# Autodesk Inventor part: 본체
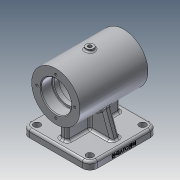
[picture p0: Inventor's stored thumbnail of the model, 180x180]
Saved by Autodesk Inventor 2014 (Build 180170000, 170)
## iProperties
Created: 2019-06
Part Number: 본체
Material: 알루미늄 6061
Document SubType Name: Modeling
Designer: net
Density: 2.71 g/cm^3
Appearance: 알루미늄 - 평지
Mass: 611.033 g
Surface Area: 626.842 cm^2
Volume: 225.474 cm^3
Author: net
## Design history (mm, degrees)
sketch "스케치1"
  geometry: L1 (-45, 0)-(45, 0); L2 (-45, 0)-(-45, 20); L3 (-45, 20)-(-45, 32); L4 (-45, 32)-(45, 32); L5 (45, 32)-(45, 20); L6 (45, 20)-(45, 0); L7 (45, 20)-(30, 20); L8 (30, 20)-(30, 17); L9 (30, 17)-(24, 17); L10 (24, 17)-(24, 25); L11 (24, 25)-(-24, 25); L12 (-24, 25)-(-24, 17); L13 (-24, 17)-(-30, 17); L14 (-30, 17)-(-30, 20); L15 (-30, 20)-(-45, 20); 1 further point
  constraints: 31 end point, 8 parallel, 5 perpendicular, 1 collinear, 1 horizontal, 1 midpoint
  dimensions: "d0" = 90 distance of L1.start L1.end; "d1" = 45 distance of L1.end point (0, 0); "d2" = 34 diameter of L13 L1; "d3" = 50 diameter of L11 L1; "d4" = 40 diameter of L7 L1; "d5" = 34 diameter of L9 L1; "d6" = 40 diameter of L15 L1; "d7" = 64 diameter of L4 L1; "d8" = 15 distance between parallel lines of L2 L14; "d9" = 48 distance between parallel lines of L10 L12; "d11" = 15 distance between parallel lines of L6 L8; "d12" = 24 horizontal distance of point (0, 0) L10.end
revolve "회전1" sketch "스케치1" stored, may be unused: angle "d13" = 90 deg
sketch "스케치2"
  geometry: L1 (0, 0)-(0, -65); L2 (0, -65)-(45, -65); L3 (45, -65)-(45, -55); L4 (45, -55)-(-45, -55); L5 (0, -65)-(-45, -65); L6 (-45, -65)-(-45, -55)
  constraints: 12 end point, 3 perpendicular, 2 parallel, 1 vertical
  dimensions: "d14" = 65 distance of L1.start L1.end; "d15" = 10 distance of L2.end L3.end; "d16" = 90 distance of L3.end L4.end; "d17" = 45 distance of L5.end L1.end
extrude "돌출1" join sketch "스케치2" stored distance "d18" = 90; taper "d19" = 0 deg
sketch "스케치3"
  geometry: L1 (0, 0)-(0, -27.268); L2 (-45, -55)-(45, -55) reference; L3 (0, -27.268)-(0, -55); L4 (0, -27.268)-(-35, -27.268); L5 (-35, -27.268)-(-35, -55); L6 (0, -55)-(-35, -55); L7 (0, -27.268)-(35, -27.268); L8 (35, -27.268)-(35, -55); L9 (0, -55)-(35, -55)
  constraints: 16 end point, 3 perpendicular, 2 collinear, 2 point on line, 1 midpoint, 1 parallel, 1 vertical
  dimensions: "d20" = 35 distance of L1.end L4.end; "d21" = 35 distance of L1.end L7.end; "d22" = 27.26751 distance of L1.start L1.end
extrude "돌출2" join sketch "스케치3" stored distance "d23" = 10; taper "d24" = 0 deg
sketch "스케치4"
  geometry: 1 further point
sketch "스케치5"
  geometry: L1 (45, -55)-(-45, -55) reference; L2 (35, -55)-(23.058, -22.189); L3 (-23.058, -22.189)-(-35, -55); A1 r 32 centre (0, 0) between (23.058, -22.189) and (-23.058, -22.189) reference; 1 further point
  constraints: 4 end point, 2 point on circle, 2 point on line
  dimensions: "d25" = 10 distance of L1.start L2.start; "d26" = 10 distance of L1.end L3.end; "d27" = 110 deg angle of L1 L3; "d28" = 110 deg angle of L1 L2
feature "리브1" dims "d29" = 1, "d30" = 10, "d31" = 0, "d32" = 0, "d33" = 1, "d34" = 1
feature "리브2" dims "d35" = 1, "d36" = 10, "d37" = 0, "d38" = 0, "d39" = 1, "d40" = 1
fillet "모깎기1" dims "d41" = 3
sketch "스케치6"
  geometry: C1 r 20 at (0, 0) reference; C2 r 32 at (0, 0) reference; A1 r 25 centre (0, 0) between (0, 25) and (25, 0); 2 further points
  constraints: 4 point on circle, 2 horizontal alignment, 2 vertical alignment, 1 centre point, 1 coincident
  dimensions: "d42" = 50 diameter of A1
hole "구멍1" sketch "스케치6" at (0, 25), (25, 0), (0, -25), (-25, 0) diameter "d43" = 3.242; stored, may be unused: countersink angle "d47" = 90 deg, drill point angle "d49" = 118 deg; dims "d44" = 7, "d45" = 4, "d46" = 2, "d48" = 9
sketch "스케치7"
  geometry: C1 r 1.621 at (0, -25) reference; C2 r 1.621 at (-25, 0) reference; C3 r 1.621 at (0, 25) reference; C4 r 1.621 at (25, 0) reference; 4 further points
  constraints: 4 coincident
hole "구멍2" sketch "스케치7" at (0, -25), (-25, 0), (0, 25), (25, 0) diameter "d50" = 3.242; stored, may be unused: countersink angle "d54" = 90 deg, drill point angle "d56" = 118 deg; dims "d51" = 7, "d52" = 4, "d53" = 2, "d55" = 9
sketch "스케치8"
  geometry: L1 (0, 0)-(0, 35); L2 (-45, 32)-(45, 32) reference
  constraints: 2 end point, 1 vertical
  dimensions: "d57" = 3 distance from line of L2 L1.end
node "작업 평면1"
sketch "스케치9"
  geometry: C1 r 5 at (0, 0); 1 further point
  constraints: 1 centre point, 1 coincident
  dimensions: "d58" = 10 diameter of C1
extrude "돌출3" join sketch "스케치9" distance "d59" = 6; taper "d60" = 0 deg
sketch "스케치10"
  geometry: C1 r 5 at (0, 0) reference
hole "구멍3" sketch "스케치10" at (0, 0) diameter "d61" = 4.917; stored, may be unused: countersink angle "d65" = 90 deg, drill point angle "d67" = 118 deg; dims "d62" = 14, "d63" = 4, "d64" = 2, "d66" = 15
sketch "스케치12"
  geometry: L1 (0, 0)-(90, 0) reference; L2 (0, -90)-(0, 0) reference; C1 r 4.5 at (10, -10); C2 r 4.5 at (80, -10); C3 r 4.5 at (10, -80); C4 r 4.5 at (80, -80); 1 further point
  constraints: 4 centre point, 1 horizontal, 1 vertical, 6 other
  dimensions: "d68" = 9 diameter of C1; "d69" = 10 distance from line of L2 C1.centre; "d70" = 10 distance from line of L1 C1.centre; "d73" = 70 distance of C1.centre C2.centre; "d76" = 70 distance of C1.centre C3.centre
extrude "돌출4" cut sketch "스케치12" stored distance "d79" = 6; taper "d80" = 0 deg
sketch "스케치13"
  geometry: L1 (90, 0)-(0, 0) reference; L2 (90, 90)-(0, 90) reference; L3 (5, 5)-(18.66, 5); L4 (85, 5)-(85, 18.66); L5 (85, 85)-(71.34, 85); L6 (5, 85)-(5, 71.34); L7 (5, 5)-(85, 85); L8 (85, 5)-(5, 85); L9 (5, 18.66)-(5, 5); L10 (18.66, 5)-(71.34, 5); L11 (71.34, 85)-(18.66, 85); L12 (85, 71.34)-(85, 85); L13 (18.66, 85)-(5, 85); L14 (5, 71.34)-(5, 18.66); L15 (85, 18.66)-(85, 71.34); L16 (71.34, 5)-(85, 5); C1 r 4.5 at (80, 10) reference; C2 r 4.5 at (80, 80) reference; C3 r 4.5 at (10, 80) reference; C4 r 4.5 at (10, 10) reference; A1 r 10 centre (10, 80) between (10, 90) and (5, 71.34); A2 r 10 centre (80, 10) between (80, 0) and (85, 18.66); A3 r 10 centre (10, 10) between (5, 18.66) and (18.66, 5); A4 r 10 centre (10, 80) between (18.66, 85) and (10, 90); A5 r 10 centre (10, 80) between (5, 71.34) and (18.66, 85); A6 r 10 centre (80, 10) between (71.34, 5) and (80, 0); A7 r 10 centre (80, 10) between (85, 18.66) and (71.34, 5); A8 r 10 centre (10, 10) between (17.071, 17.071) and (5, 18.66); A9 r 10 centre (10, 10) between (18.66, 5) and (17.071, 17.071); A10 r 10 centre (80, 80) between (71.34, 85) and (85, 71.34); A11 r 10 centre (80, 80) between (80, 90) and (71.34, 85); A12 r 10 centre (80, 80) between (85, 71.34) and (80, 90); 1 further point
  constraints: 28 end point, 24 point on circle, 18 parallel, 12 centre point, 9 perpendicular, 5 point on line, 4 coincident, 3 horizontal, 2 midpoint, 1 equal radius
  dimensions: "d81" = 80 distance of L6.start L3.start; "d82" = 80 distance of L5.start L6.start; "d84" = 20 diameter of A1; "d87" = 20 diameter of A10; "d88" = 10 radius of A7
extrude "돌출5" cut sketch "스케치13" distance "d89" = 5; taper "d90" = 0 deg
fillet "모깎기2" dims "d91" = 2
fillet "모깎기3" dims "d92" = 3
chamfer "모따기1" distance "d93" = 1; stored, may be unused: second distance "d94" = 2, angle "d95" = 45 deg
fillet "모깎기4" dims "d96" = 0.6
fillet "모깎기5" dims "d97" = 3
fillet "모깎기6" dims "d98" = 3
fillet "모깎기7" dims "d99" = 3
fillet "모깎기8" dims "d100" = 10
fillet "모깎기9" dims "d101" = 3
node "작업 평면2"
sketch "스케치14"
  geometry: L1 (45, -65)-(45, -58) reference; L2 (-35, -65)-(35, -65) reference; 2 further points
  constraints: 1 other
  dimensions: "d103" = 45 distance from line of L1 point (0, -61); "d104" = 4 distance from line of L2 point (0, -61)
feature "엠보싱1" sketch "스케치14" dims "d1" = 45, "d105" = 0.5, "d106" = 0
fillet "모깎기10" dims "d107" = 3
node "솔리드1"
other parameters: "d102" = 48.75
